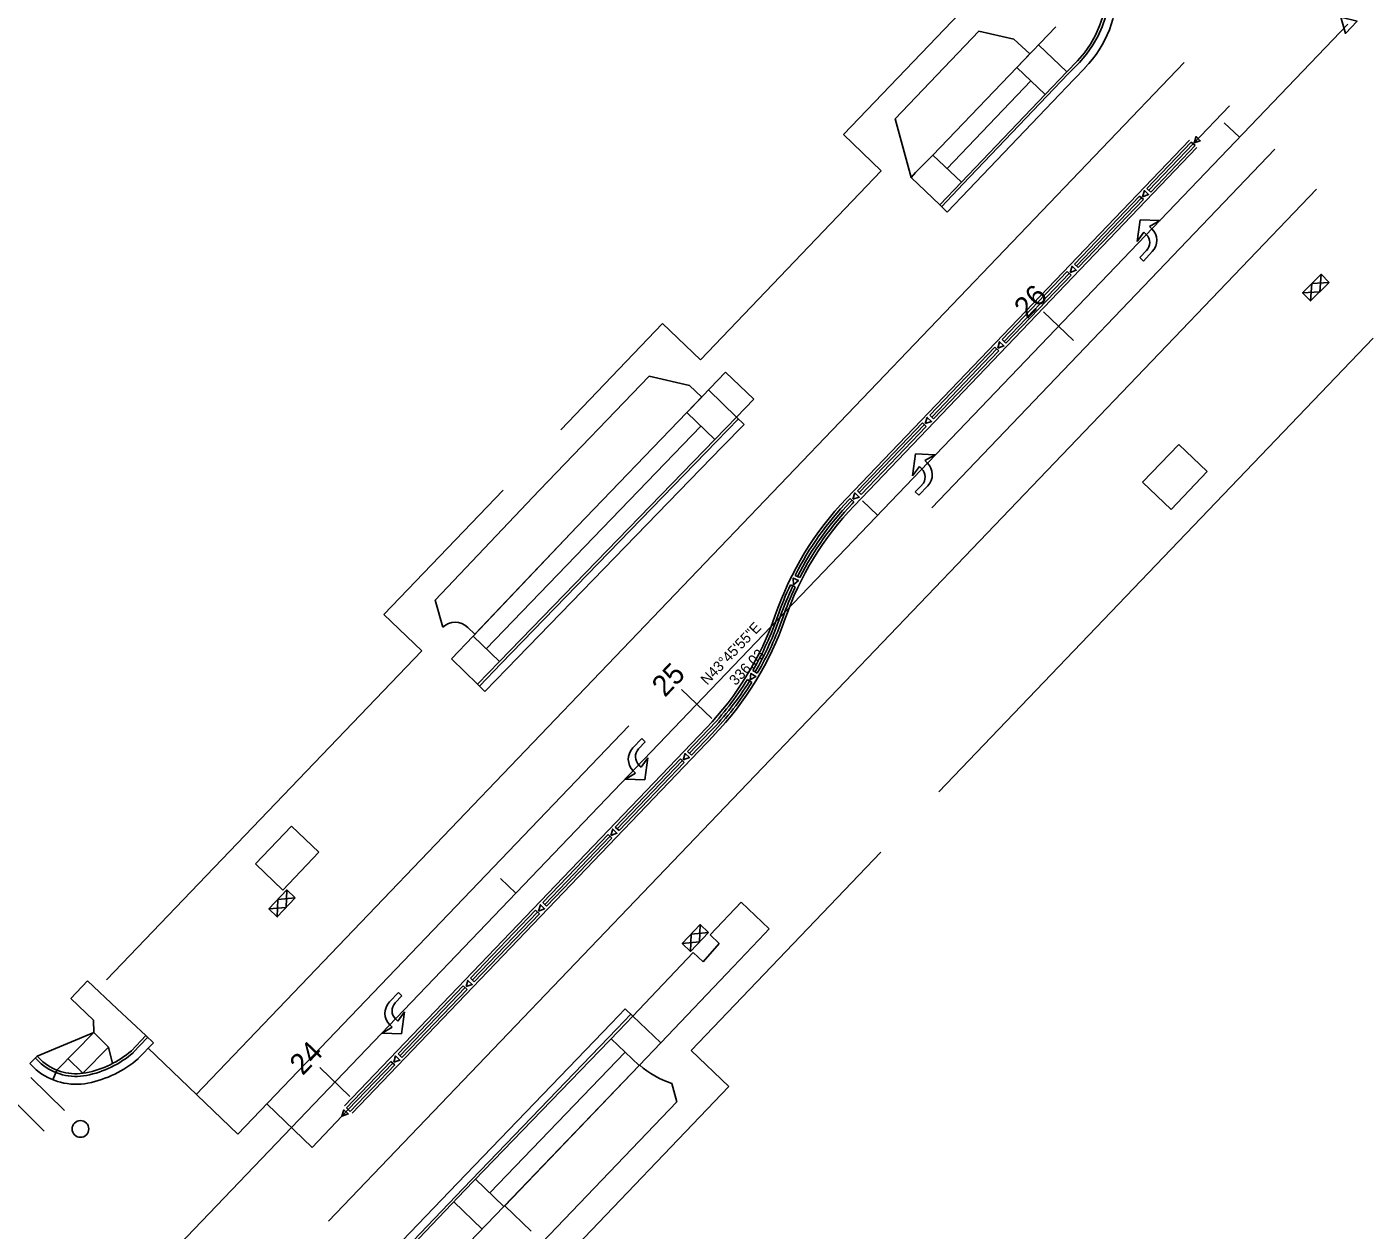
# Model space of a CAD drawing. Extents: x 2377903 to 2496516, y 664638 to 732785.
# Drawn here: x 2378820.2 to 2379077.5, y 731077.2 to 731307 of the extents above; entities that cross this region are included whole.
import ezdxf

# ---------------------------------------------------------------- set-up
doc = ezdxf.new("R2010")
doc.units = 0
for name, color, linetype in [('ALG_CL_BLUE_Horiz', 7, 'Continuous'), ('ALG_CL_BLUE_Horiz-Stationing', 7, 'Continuous'), ('ALG_CL_BLUE_Horiz-Text', 7, 'Continuous'), ('Default', 7, 'Continuous'), ('DES_ROADWAY_Approach', 7, 'Continuous'), ('DES_ROADWAY_Curb-Back', 7, 'Continuous'), ('DES_ROADWAY_Curb-Face', 7, 'Continuous'), ('DES_ROADWAY_Curb-Face-LINE STYLE', 7, 'Continuous'), ('DES_ROADWAY_Edge-of-Pavement', 7, 'Continuous'), ('DES_ROADWAY_Sidewalk', 7, 'Continuous'), ('ENV_EROSN_Temp-Erosn-Ctrl-Details', 7, 'Continuous'), ('ROW_P_PUA', 7, 'Continuous'), ('TOPO_WTRUTIL_Valve', 7, 'Continuous'), ('TRAF_PAVEMARK_Arrows', 7, 'Continuous'), ('TRAF_PAVEMARK_Stop-Bar', 7, 'Continuous'), ('TRAF_PAVEMARK_White_8-IN', 7, 'Continuous'), ('TRAF_PAVEMARK_White_SKIP 12-38', 7, 'Continuous'), ('TRAF_PAVEMARK_Yellow', 7, 'Continuous'), ('TRAF_PAVEMARK_Yellow-DBL YELLOW', 7, 'Continuous'), ('TRAF_WORKZONE_Drum', 7, 'Continuous')]:
    doc.layers.add(name, color=color, linetype=linetype)

msp = doc.modelspace()

# ---------------------------------------------------------------- linework, layer by layer
at = {"layer": 'ALG_CL_BLUE_Horiz'}
msp.add_line((2378840.27, 731064.93), (2379072.7, 731307.6), dxfattribs=at)
at = {"layer": 'ALG_CL_BLUE_Horiz-Stationing'}
for p, q in [((2379049.11, 731288.75), (2379052, 731285.99)), ((2379014.53, 731252.64), (2379020.3, 731247.11)), ((2378979.94, 731216.53), (2378982.83, 731213.77)), ((2378945.36, 731180.43), (2378951.13, 731174.89)), ((2378910.77, 731144.32), (2378913.66, 731141.55)), ((2378876.19, 731108.21), (2378881.96, 731102.67))]:
    msp.add_line(p, q, dxfattribs=at)
msp.add_lwpolyline([(2379071.37, 731308.88), (2379072.26, 731305.81), (2379074.48, 731308.12)], close=True, dxfattribs=at)
at = {"layer": 'Default'}
for p, q in [((2378996.13, 731279.97), (2379012.13, 731296.72)), ((2378908.03, 731188.21), (2378949.04, 731230.77)), ((2378908.7, 731084.28), (2378934.56, 731111.16))]:
    msp.add_line(p, q, dxfattribs=at)
at = {"layer": 'DES_ROADWAY_Approach'}
msp.add_lwpolyline([(2379011.94, 731301.9), (2379009.42, 731299.3), (2378993.42, 731282.56), (2378990.1, 731279.2), (2378989.22, 731278.28), (2378986.19, 731289.48), (2379002.2, 731306.21), (2379008.87, 731304.69)], close=True, dxfattribs=at)
for points in [[(2378899.7, 731192.37), (2378898.27, 731197.51), (2378918.14, 731218.47), (2378918.2, 731218.52), (2378939.18, 731240.29), (2378946.9, 731238.53), (2378949.21, 731236.32), (2378946.38, 731233.35), (2378925.4, 731211.58), (2378905.87, 731191), (2378904.49, 731192.32)], [(2378916.59, 731076.99), (2378911.55, 731081.82), (2378937.23, 731108.59), (2378937.35, 731108.71)], [(2378943.49, 731105.18), (2378944.45, 731101.66), (2378918.62, 731074.75), (2378918.32, 731074.82)]]:
    msp.add_lwpolyline(points, dxfattribs=at)
for centre, radius, start, end in [((2378902.07, 731189.79), 3.5, 46.2032, 132.6648), ((2378948.78, 731121.47), 17.13, 228.1555, 252.0128)]:
    msp.add_arc(centre, radius, start, end, dxfattribs=at)
at = {"layer": 'DES_ROADWAY_Curb-Back'}
for p, q in [((2379034.67, 731275.84), (2379043.16, 731284.71)), ((2379020.83, 731261.4), (2379033.28, 731274.4)), ((2379007, 731246.95), (2379019.45, 731259.95)), ((2378993.17, 731232.51), (2379005.62, 731245.51)), ((2378979.33, 731218.07), (2378991.78, 731231.07)), ((2378977.61, 731216.26), (2378977.95, 731216.62)), ((2378946.87, 731168.28), (2378950.83, 731172.41)), ((2378933.04, 731153.83), (2378945.49, 731166.83)), ((2378919.21, 731139.39), (2378931.66, 731152.39)), ((2378905.37, 731124.95), (2378917.82, 731137.94)), ((2378891.54, 731110.5), (2378903.99, 731123.5)), ((2378933.36, 731115.26), (2378933.36, 731115.26)), ((2378840.2, 731111.44), (2378842.93, 731114.33)), ((2378822.19, 731110.39), (2378823.29, 731109.31)), ((2378881.66, 731100.19), (2378890.15, 731109.06))]:
    msp.add_line(p, q, dxfattribs=at)
for points in [[(2378994.7, 731273.04), (2378998.85, 731277.38), (2379014.84, 731294.13), (2379018.99, 731298.47), (2379021.04, 731300.59)], [(2378906.35, 731181.47), (2378910.53, 731185.78), (2378951.71, 731228.19), (2378955.87, 731232.5)], [(2378936.04, 731118.07), (2378933.36, 731115.26), (2378903.95, 731084.78), (2378888.91, 731069.01)]]:
    msp.add_lwpolyline(points, dxfattribs=at)
for centre, radius, start, end in [((2379006.63, 731314.47), 20, 316.0745, 45.3054), ((2379020.94, 731174.76), 60, 136.2348, 152.9512), ((2379020.94, 731174.76), 60, 154.8614, 160.9588), ((2378907.5, 731213.91), 60, 329.8678, 340.9588), ((2378907.5, 731213.91), 60, 316.2348, 327.9576), ((2378827.84, 731125.82), 18.97, 281.1303, 310.6825), ((2378829.61, 731116.94), 9.91, 230.3632, 280.9931)]:
    msp.add_arc(centre, radius, start, end, dxfattribs=at)
at = {"layer": 'DES_ROADWAY_Curb-Face'}
for p, q in [((2379034.31, 731276.19), (2379042.8, 731285.05)), ((2379042.8, 731285.05), (2379043.52, 731284.36)), ((2379035.03, 731275.49), (2379043.52, 731284.36)), ((2379020.47, 731261.74), (2379032.92, 731274.74)), ((2379032.92, 731274.74), (2379033.65, 731274.05)), ((2379034.31, 731276.19), (2379035.03, 731275.49)), ((2379021.19, 731261.05), (2379033.65, 731274.05)), ((2379020.47, 731261.74), (2379021.19, 731261.05)), ((2379006.64, 731247.3), (2379019.09, 731260.3)), ((2379007.36, 731246.61), (2379019.81, 731259.61)), ((2379019.09, 731260.3), (2379019.81, 731259.61)), ((2379006.64, 731247.3), (2379007.36, 731246.61)), ((2378992.8, 731232.86), (2379005.26, 731245.85)), ((2378993.53, 731232.16), (2379005.98, 731245.16)), ((2379005.26, 731245.85), (2379005.98, 731245.16)), ((2378978.97, 731218.41), (2378991.42, 731231.41)), ((2378979.69, 731217.72), (2378992.14, 731230.72)), ((2378991.42, 731231.41), (2378992.14, 731230.72)), ((2378992.8, 731232.86), (2378993.53, 731232.16)), ((2378978.97, 731218.41), (2378979.69, 731217.72)), ((2378977.25, 731216.61), (2378977.59, 731216.97)), ((2378977.59, 731216.97), (2378978.31, 731216.28)), ((2378977.97, 731215.92), (2378978.31, 731216.28)), ((2378967.05, 731202.26), (2378967.95, 731201.83)), ((2378966.17, 731200.46), (2378967.07, 731200.04)), ((2378957.94, 731182.34), (2378958.79, 731181.81)), ((2378958.97, 731184.06), (2378959.84, 731183.56)), ((2378946.51, 731168.62), (2378950.47, 731172.76)), ((2378947.24, 731167.93), (2378951.19, 731172.06)), ((2378932.68, 731154.18), (2378945.13, 731167.18)), ((2378933.4, 731153.49), (2378945.85, 731166.49)), ((2378945.13, 731167.18), (2378945.85, 731166.49)), ((2378946.51, 731168.62), (2378947.24, 731167.93)), ((2378932.68, 731154.18), (2378933.4, 731153.49)), ((2378918.85, 731139.73), (2378931.3, 731152.73)), ((2378919.57, 731139.04), (2378932.02, 731152.04)), ((2378931.3, 731152.73), (2378932.02, 731152.04)), ((2378905.01, 731125.29), (2378917.46, 731138.29)), ((2378917.46, 731138.29), (2378918.18, 731137.6)), ((2378918.85, 731139.73), (2378919.57, 731139.04)), ((2378905.73, 731124.6), (2378918.18, 731137.6)), ((2378905.01, 731125.29), (2378905.73, 731124.6)), ((2378891.18, 731110.85), (2378903.63, 731123.85)), ((2378891.9, 731110.16), (2378904.35, 731123.15)), ((2378903.63, 731123.85), (2378904.35, 731123.15)), ((2378891.18, 731110.85), (2378891.9, 731110.16)), ((2378881.3, 731100.54), (2378889.79, 731109.4)), ((2378882.02, 731099.85), (2378890.52, 731108.71)), ((2378889.79, 731109.4), (2378890.52, 731108.71)), ((2378881.3, 731100.54), (2378882.02, 731099.85))]:
    msp.add_line(p, q, dxfattribs=at)
for centre, radius, start, end in [((2379020.94, 731174.76), 60.5, 136.2348, 152.967), ((2379020.94, 731174.76), 59.5, 136.2348, 152.9351), ((2379020.94, 731174.76), 60.5, 154.8614, 160.9588), ((2379020.94, 731174.76), 59.5, 154.8614, 160.9588), ((2378907.5, 731213.91), 59.5, 329.8839, 340.9588), ((2378907.5, 731213.91), 60.5, 329.8839, 340.9588), ((2378907.5, 731213.91), 59.5, 316.2348, 327.9576), ((2378907.5, 731213.91), 60.5, 316.2348, 327.9576)]:
    msp.add_arc(centre, radius, start, end, dxfattribs=at)
at = {"layer": 'DES_ROADWAY_Curb-Face-LINE STYLE'}
for points in [[(2378995.06, 731272.7), (2378999.21, 731277.04), (2379015.2, 731293.79), (2379019.35, 731298.12), (2379021.4, 731300.25)], [(2378906.71, 731181.12), (2378910.89, 731185.43), (2378952.06, 731227.84), (2378956.23, 731232.15)], [(2378935.68, 731118.42), (2378933, 731115.61), (2378903.59, 731085.13), (2378888.55, 731069.36)], [(2378840.53, 731111.06), (2378840.55, 731111.08), (2378843.3, 731113.99)], [(2378821.84, 731110.04), (2378822.95, 731108.94), (2378822.97, 731108.92)], [(2378831.59, 731106.72), (2378831.59, 731106.72), (2378831.59, 731106.72)]]:
    msp.add_lwpolyline(points, dxfattribs=at)
for centre, radius, start, end in [((2379006.63, 731314.47), 20.5, 316.0745, 45.3054), ((2378827.84, 731125.82), 19.47, 281.1303, 310.6825), ((2378829.61, 731116.94), 10.41, 230.3632, 280.9931)]:
    msp.add_arc(centre, radius, start, end, dxfattribs=at)
at = {"layer": 'DES_ROADWAY_Edge-of-Pavement'}
for p, q in [((2378994.7, 731273.04), (2378996.15, 731271.66)), ((2378955.87, 731232.5), (2378957.31, 731231.11)), ((2378906.35, 731181.47), (2378907.78, 731180.08)), ((2378934.6, 731119.46), (2378936.04, 731118.07)), ((2378842.93, 731114.33), (2378844.39, 731112.96)), ((2378822.19, 731110.39), (2378820.78, 731108.97)), ((2378825.91, 731107.75), (2378825.17, 731105.89))]:
    msp.add_line(p, q, dxfattribs=at)
for points in [[(2379022.48, 731299.2), (2379020.43, 731297.08), (2379016.28, 731292.75), (2379000.29, 731276), (2378996.15, 731271.66)], [(2378957.31, 731231.11), (2378953.14, 731226.79), (2378911.96, 731184.38), (2378907.78, 731180.08)], [(2378887.45, 731070.38), (2378902.51, 731086.16), (2378931.92, 731116.64), (2378934.6, 731119.46)], [(2378841.5, 731109.92), (2378841.58, 731109.99), (2378844.39, 731112.96)], [(2378820.78, 731108.97), (2378821.94, 731107.82), (2378822.01, 731107.77)], [(2378831.88, 731105.25), (2378831.88, 731105.25), (2378831.88, 731105.25)]]:
    msp.add_lwpolyline(points, dxfattribs=at)
for centre, radius, start, end in [((2379006.63, 731314.47), 22, 316.0675, 45.3054), ((2378827.84, 731125.82), 20.97, 281.1303, 310.6825), ((2378829.61, 731116.94), 11.91, 230.3632, 280.9931)]:
    msp.add_arc(centre, radius, start, end, dxfattribs=at)
at = {"layer": 'DES_ROADWAY_Sidewalk'}
for p, q in [((2379009.42, 731299.3), (2379016.93, 731307.04)), ((2379013.6, 731303.61), (2379018.99, 731298.47)), ((2379009.42, 731299.3), (2378993.42, 731282.56)), ((2379009.42, 731299.3), (2379014.84, 731294.13)), ((2378993.42, 731282.56), (2378990.1, 731279.2)), ((2378993.42, 731282.56), (2378998.85, 731277.38)), ((2378990.1, 731279.2), (2378989.22, 731278.28)), ((2378989.22, 731278.28), (2378994.7, 731273.04)), ((2378946.38, 731233.35), (2378953.75, 731241.08)), ((2378959.15, 731235.93), (2378953.75, 731241.08)), ((2378950.52, 731237.7), (2378955.87, 731232.5)), ((2378959.15, 731235.93), (2378955.87, 731232.5)), ((2378925.4, 731211.58), (2378946.38, 731233.35)), ((2378946.38, 731233.35), (2378951.71, 731228.19)), ((2379040.4, 731227.29), (2379033.48, 731220.07)), ((2379045.83, 731222.09), (2379040.4, 731227.29)), ((2379038.92, 731214.86), (2379045.83, 731222.09)), ((2379038.92, 731214.86), (2379033.48, 731220.07)), ((2378905.53, 731190.63), (2378925.4, 731211.58)), ((2378901.38, 731186.3), (2378905.53, 731190.63)), ((2378905.53, 731190.63), (2378910.53, 731185.78)), ((2378901.38, 731186.3), (2378906.35, 731181.47)), ((2378870.82, 731154.37), (2378863.9, 731147.14)), ((2378876.03, 731149.37), (2378870.82, 731154.37)), ((2378869.16, 731142.1), (2378876.03, 731149.37)), ((2378869.16, 731142.1), (2378863.9, 731147.14)), ((2378950.8, 731133.6), (2378956.75, 731139.85)), ((2378962.11, 731134.73), (2378956.75, 731139.85)), ((2378950.8, 731133.6), (2378952.54, 731131.93)), ((2378955.21, 731127.49), (2378961.26, 731133.85)), ((2378961.26, 731133.85), (2378962.11, 731134.73)), ((2378936.04, 731118.07), (2378947.57, 731130.19)), ((2378949.46, 731128.44), (2378947.57, 731130.19)), ((2378952.54, 731131.93), (2378949.46, 731128.44)), ((2378941.37, 731112.93), (2378955.21, 731127.49)), ((2378828.6, 731121.39), (2378831.83, 731124.82)), ((2378831.83, 731124.82), (2378837.5, 731119.47)), ((2378832.94, 731117.29), (2378828.6, 731121.39)), ((2378832.99, 731114.91), (2378832.94, 731117.29)), ((2378837.5, 731119.47), (2378842.93, 731114.33)), ((2378941.37, 731112.93), (2378936.04, 731118.07)), ((2378832.99, 731114.91), (2378822.19, 731110.39)), ((2378832.99, 731114.91), (2378825.91, 731107.75)), ((2378835.83, 731112.1), (2378832.99, 731114.91)), ((2378937.23, 731108.59), (2378931.89, 731113.74)), ((2378937.23, 731108.59), (2378941.37, 731112.93)), ((2378830.91, 731107.12), (2378828.07, 731109.93)), ((2378835.83, 731112.1), (2378830.91, 731107.12)), ((2378835.83, 731112.1), (2378836.61, 731109.01)), ((2378937.23, 731108.59), (2378911.41, 731081.67)), ((2378911.41, 731081.67), (2378906, 731086.9)), ((2378899.02, 731068.85), (2378911.41, 731081.67)), ((2378907.24, 731077.36), (2378901.84, 731082.57))]:
    msp.add_line(p, q, dxfattribs=at)
at = {"layer": 'ENV_EROSN_Temp-Erosn-Ctrl-Details'}
for points in [[(2379069.17, 731258.21), (2379065.6, 731254.7), (2379064.06, 731256.27), (2379067.62, 731259.78)], [(2378871.5, 731140.65), (2378868.07, 731137.01), (2378866.47, 731138.52), (2378869.9, 731142.16)], [(2378950.53, 731134.03), (2378947.08, 731130.41), (2378945.49, 731131.92), (2378948.93, 731135.55)]]:
    msp.add_lwpolyline(points, close=True, dxfattribs=at)
for points in [[(2379067.62, 731259.78), (2379067.38, 731256.46), (2379064.06, 731256.27)], [(2379065.6, 731254.7), (2379065.84, 731258.03), (2379069.17, 731258.21)], [(2378869.9, 731142.16), (2378869.79, 731138.83), (2378866.47, 731138.52)], [(2378868.07, 731137.01), (2378868.19, 731140.34), (2378871.5, 731140.65)], [(2378948.93, 731135.55), (2378948.8, 731132.22), (2378945.49, 731131.92)], [(2378947.08, 731130.41), (2378947.21, 731133.73), (2378950.53, 731134.03)]]:
    msp.add_lwpolyline(points, dxfattribs=at)
at = {"layer": 'ROW_P_PUA'}
for p, q in [((2378976.31, 731286.48), (2379005.32, 731316.76)), ((2378976.31, 731286.48), (2378983.53, 731279.56)), ((2378948.95, 731243.45), (2378983.53, 731279.56)), ((2378922.31, 731230.09), (2378941.73, 731250.37)), ((2378941.73, 731250.37), (2378948.95, 731243.45)), ((2378994.53, 731160.92), (2379077.54, 731247.6)), ((2378888.47, 731194.76), (2378911.24, 731218.54)), ((2378888.47, 731194.76), (2378895.69, 731187.84)), ((2378835.45, 731124.95), (2378895.69, 731187.84)), ((2378947.2, 731111.51), (2378983.46, 731149.37)), ((2378954.42, 731104.59), (2378947.2, 731111.51)), ((2378907.67, 731055.78), (2378954.42, 731104.59))]:
    msp.add_line(p, q, dxfattribs=at)
at = {"layer": 'TOPO_WTRUTIL_Valve'}
msp.add_circle((2378830.45, 731096.49), 1.6, dxfattribs=at)
at = {"layer": 'TRAF_PAVEMARK_Arrows'}
for p, q in [((2379033.02, 731270.21), (2379032.45, 731266.03)), ((2379036.76, 731270.07), (2379033.02, 731270.21)), ((2379034.8, 731268.93), (2379036.76, 731270.07)), ((2379032.45, 731266.03), (2379033.73, 731267.81)), ((2379033.73, 731267.81), (2379034.18, 731267.38)), ((2379035.25, 731268.5), (2379034.8, 731268.93)), ((2379034.24, 731264.31), (2379032.95, 731262.96)), ((2379033.63, 731262.32), (2379035.34, 731264.11)), ((2379032.95, 731262.96), (2379033.63, 731262.32)), ((2378990.1, 731225.45), (2378989.53, 731221.27)), ((2378993.84, 731225.31), (2378990.1, 731225.45)), ((2378989.53, 731221.27), (2378990.81, 731223.05)), ((2378990.81, 731223.05), (2378991.26, 731222.63)), ((2378991.88, 731224.18), (2378993.84, 731225.31)), ((2378992.33, 731223.75), (2378991.88, 731224.18)), ((2378991.32, 731219.55), (2378990.03, 731218.21)), ((2378990.03, 731218.21), (2378990.71, 731217.56)), ((2378990.71, 731217.56), (2378992.42, 731219.36)), ((2378937.76, 731171.09), (2378936.04, 731169.29)), ((2378937.14, 731169.1), (2378938.43, 731170.44)), ((2378938.43, 731170.44), (2378937.76, 731171.09)), ((2378938.93, 731167.38), (2378937.65, 731165.6)), ((2378938.36, 731163.2), (2378938.93, 731167.38)), ((2378936.58, 731164.48), (2378934.63, 731163.34)), ((2378936.13, 731164.9), (2378936.58, 731164.48)), ((2378937.65, 731165.6), (2378937.2, 731166.02)), ((2378934.63, 731163.34), (2378938.36, 731163.2)), ((2378891.23, 731122.56), (2378889.52, 731120.77)), ((2378891.91, 731121.92), (2378891.23, 731122.56)), ((2378890.62, 731120.57), (2378891.91, 731121.92)), ((2378891.13, 731117.07), (2378890.68, 731117.5)), ((2378892.41, 731118.85), (2378891.13, 731117.07)), ((2378891.84, 731114.67), (2378892.41, 731118.85)), ((2378890.06, 731115.95), (2378888.1, 731114.81)), ((2378888.1, 731114.81), (2378891.84, 731114.67)), ((2378889.61, 731116.38), (2378890.06, 731115.95))]:
    msp.add_line(p, q, dxfattribs=at)
for centre, radius, start, end in [((2379032.67, 731265.81), 2.17, 316.2016, 46.2016), ((2379033.1, 731266.26), 3.1, 316.2016, 46.2016), ((2378990.18, 731221.5), 3.1, 316.2016, 46.2016), ((2378989.75, 731221.06), 2.17, 316.2016, 46.2016), ((2378938.28, 731167.15), 3.1, 136.2016, 226.2016), ((2378938.71, 731167.59), 2.17, 136.2016, 226.2016), ((2378891.76, 731118.62), 3.1, 136.2016, 226.2016), ((2378892.19, 731119.07), 2.17, 136.2016, 226.2016)]:
    msp.add_arc(centre, radius, start, end, dxfattribs=at)
at = {"layer": 'TRAF_PAVEMARK_Stop-Bar'}
for p, q in [((2378843.36, 731111.96), (2378860.55, 731095.49)), ((2378827.39, 731100), (2378820.99, 731106.32)), ((2378823.53, 731096.08), (2378817.12, 731102.41)), ((2378866.08, 731101.27), (2378874.75, 731092.97))]:
    msp.add_line(p, q, dxfattribs=at)
at = {"layer": 'TRAF_PAVEMARK_White_8-IN'}
for p, q in [((2378993.19, 731215.19), (2379058.77, 731283.66)), ((2378860.55, 731095.49), (2378935.25, 731173.49))]:
    msp.add_line(p, q, dxfattribs=at)
at = {"layer": 'TRAF_PAVEMARK_White_SKIP 12-38'}
for p, q in [((2378852.6, 731103.1), (2379041.44, 731300.26)), ((2378877.88, 731078.89), (2379066.71, 731276.05))]:
    msp.add_line(p, q, dxfattribs=at)
at = {"layer": 'TRAF_PAVEMARK_Yellow'}
for p, q in [((2378976.88, 731216.96), (2379042.44, 731285.4)), ((2378978.33, 731215.57), (2379043.88, 731284.01)), ((2378880.94, 731100.88), (2378950.11, 731173.1)), ((2378882.39, 731099.5), (2378951.56, 731171.72))]:
    msp.add_line(p, q, dxfattribs=at)
for centre, radius, start, end in [((2379020.94, 731174.76), 61, 136.2348, 160.9588), ((2379020.94, 731174.76), 59, 136.2348, 160.9588), ((2378907.5, 731213.91), 59, 316.2348, 340.9588), ((2378907.5, 731213.91), 61, 316.2348, 340.9588)]:
    msp.add_arc(centre, radius, start, end, dxfattribs=at)
at = {"layer": 'TRAF_PAVEMARK_Yellow-DBL YELLOW'}
for p, q in [((2379043.16, 731284.71), (2379050.1, 731291.96)), ((2378874.75, 731092.97), (2378881.66, 731100.19))]:
    msp.add_line(p, q, dxfattribs=at)
at = {"layer": 'TRAF_WORKZONE_Drum'}
for points in [[(2379043.33, 731284.89), (2379043.7, 731286.09), (2379044.52, 731285.31)], [(2379033.46, 731274.58), (2379033.83, 731275.78), (2379034.64, 731275)], [(2379019.62, 731260.13), (2379020, 731261.33), (2379020.81, 731260.56)], [(2379005.79, 731245.69), (2379006.16, 731246.89), (2379006.97, 731246.11)], [(2378991.95, 731231.25), (2378992.33, 731232.45), (2378993.14, 731231.67)], [(2378978.12, 731216.8), (2378978.49, 731218), (2378979.31, 731217.23)], [(2378966.73, 731200.48), (2378966.7, 731201.73), (2378967.71, 731201.26)], [(2378958.49, 731182.29), (2378958.62, 731183.54), (2378959.57, 731182.95)], [(2378945.66, 731167.01), (2378946.04, 731168.21), (2378946.85, 731167.44)], [(2378931.83, 731152.57), (2378932.2, 731153.77), (2378933.01, 731152.99)], [(2378918, 731138.13), (2378918.37, 731139.33), (2378919.18, 731138.55)], [(2378904.16, 731123.68), (2378904.53, 731124.88), (2378905.35, 731124.1)], [(2378890.33, 731109.24), (2378890.7, 731110.44), (2378891.51, 731109.66)], [(2378880.45, 731098.93), (2378880.82, 731100.13), (2378881.64, 731099.35)]]:
    msp.add_lwpolyline(points, close=True, dxfattribs=at)

# ---------------------------------------------------------------- texts
at = {"layer": 'ALG_CL_BLUE_Horiz-Stationing'}
for s, p in [('26', (2379011.42, 731251.13)), ('25', (2378942.18, 731178.84)), ('24', (2378872.94, 731106.56))]:
    msp.add_text(s, height=4, rotation=46.2348, dxfattribs=at).set_placement(p)
at = {"layer": 'ALG_CL_BLUE_Horiz-Text'}
for s, p in [('N43°45\'55"E', (2378950.24, 731181.19)), ('336.03', (2378955.7, 731181.1))]:
    msp.add_text(s, height=2, rotation=46.2348, dxfattribs=at).set_placement(p)

doc.saveas('drawing.dxf')
